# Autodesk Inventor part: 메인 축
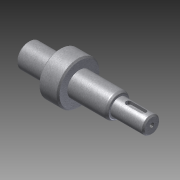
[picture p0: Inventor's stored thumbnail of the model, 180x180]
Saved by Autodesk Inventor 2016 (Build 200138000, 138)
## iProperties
Created: 2016-04
Part Number: 메인 축
Document SubType Name: Modeling
Designer: mdu
Density: 7.86 g/cm^3
Mass: 230.24 g
Surface Area: 74.3518 cm^2
Volume: 29.2926 cm^3
Material: 강철, 연강
Appearance: 금속-강(스테인리스, 브러시됨)
Author: mdu
Revision Number: 1
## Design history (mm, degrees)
sketch "스케치1"
  geometry: L1 (10.497, -57.5)-(97.497, -57.5); L2 (10.497, -66)-(32.497, -66); L3 (32.497, -72.5)-(46.5, -72.5); L4 (46.5, -66)-(74.497, -66); L5 (97.497, -63.5)-(97.497, -57.5); L6 (10.497, -66)-(10.497, -57.5); L7 (46.5, -69.749)-(46.5, -45.251) reference; L8 (46.5, -72.5)-(46.5, -66); L9 (32.497, -72.5)-(32.497, -66); L10 (32.497, -35)-(32.497, -80) reference; L11 (97.497, -63.5)-(74.497, -63.5); L12 (74.497, -63.5)-(74.497, -66); 3 further points
  constraints: 20 end point, 4 perpendicular, 3 point on line, 2 parallel, 1 collinear, 1 horizontal, 1 midpoint
  dimensions: "d0" = 17 diameter of L4 L1; "d1" = 30 diameter of L3 L1; "d2" = 22 distance of L2.start L2.end; "d5" = 17 diameter of L2 L1; "d19" = 65 distance between parallel lines of L5 L9; "d21" = 50.99692 distance between parallel lines of L5 L8 (derived); "d22" = 23 distance between parallel lines of L5 L12; "d23" = 12 diameter of L11 L1
revolve "회전1" sketch "스케치1" stored, may be unused: angle "d4" = 90 deg
chamfer "모따기1" distance "d6" = 1; stored, may be unused: second distance "d7" = 2, angle "d8" = 45 deg
node "작업 평면1"
sketch "스케치2"
  geometry: L1 (10.497, -65)-(10.497, -50) reference; L2 (16.997, -55)-(25.997, -55); L3 (25.997, -60)-(16.997, -60); A1 r 2.5 centre (25.997, -57.5) between (25.997, -60) and (25.997, -55); A2 r 2.5 centre (16.997, -57.5) between (16.997, -55) and (16.997, -60); 2 further points
  constraints: 4 end point, 4 point on circle, 4 tangent, 2 centre point, 1 horizontal alignment, 1 midpoint, 1 parallel, 1 perpendicular
  dimensions: "d9" = 5 distance between parallel lines of L3 L2; "d10" = 14 dimension on A1 A2; "d11" = 4 distance edge to line of A2 L1
extrude "돌출1" cut sketch "스케치2" distance "d12" = 3; taper "d13" = 0 deg
node "작업 평면2"
sketch "스케치3"
  geometry: L1 (91.497, -55.5)-(81.497, -55.5); L2 (81.497, -59.5)-(91.497, -59.5); L3 (97.497, -52.5)-(97.497, -62.5) reference; A1 r 2 centre (81.497, -57.5) between (81.497, -55.5) and (81.497, -59.5); A2 r 2 centre (91.497, -57.5) between (91.497, -59.5) and (91.497, -55.5); 4 further points
  constraints: 4 end point, 4 point on circle, 4 tangent, 2 centre point, 2 horizontal, 2 point on line, 1 horizontal alignment, 1 midpoint, 1 vertical alignment
  dimensions: "d32" = 14 dimension on A2 A1; "d34" = 4 distance edge to line of A2 L3; "d35" = 4 distance between parallel lines of L2 L1
extrude "돌출2" cut sketch "스케치3" distance "d16" = 2.5; taper "d17" = 0 deg
sketch "스케치4"
  geometry: L1 (74.497, -50.05)-(72.678, -49); L2 (74.497, -49)-(46.5, -49) reference; L3 (74.497, -49)-(74.497, -66) reference; L4 (74.497, -66)-(46.5, -66) reference; L5 (74.497, -57.5)-(60.711, -57.5); 1 further point
  constraints: 4 end point, 2 point on line, 1 midpoint, 1 parallel
  dimensions: "d24" = 14.9 diameter of L1.start L5; "d26" = 30 deg angle of L2 L1
revolve "회전2" sketch "스케치4" stored, may be unused: angle "d28" = 90 deg
fillet "모깎기1" dims "d29" = 1
fillet "모깎기2" dims "d30" = 2
hole "구멍1" diameter "d38" = 3.242; stored, may be unused: countersink angle "d42" = 90 deg, drill point angle "d44" = 118 deg; dims "d39" = 8, "d40" = 4, "d41" = 2, "d43" = 10, "d45" = 10, "d46" = 10
node "솔리드1"
node "참조4"
node "참조5"
other parameters: "d20" = 6, "d47" = -8.5
